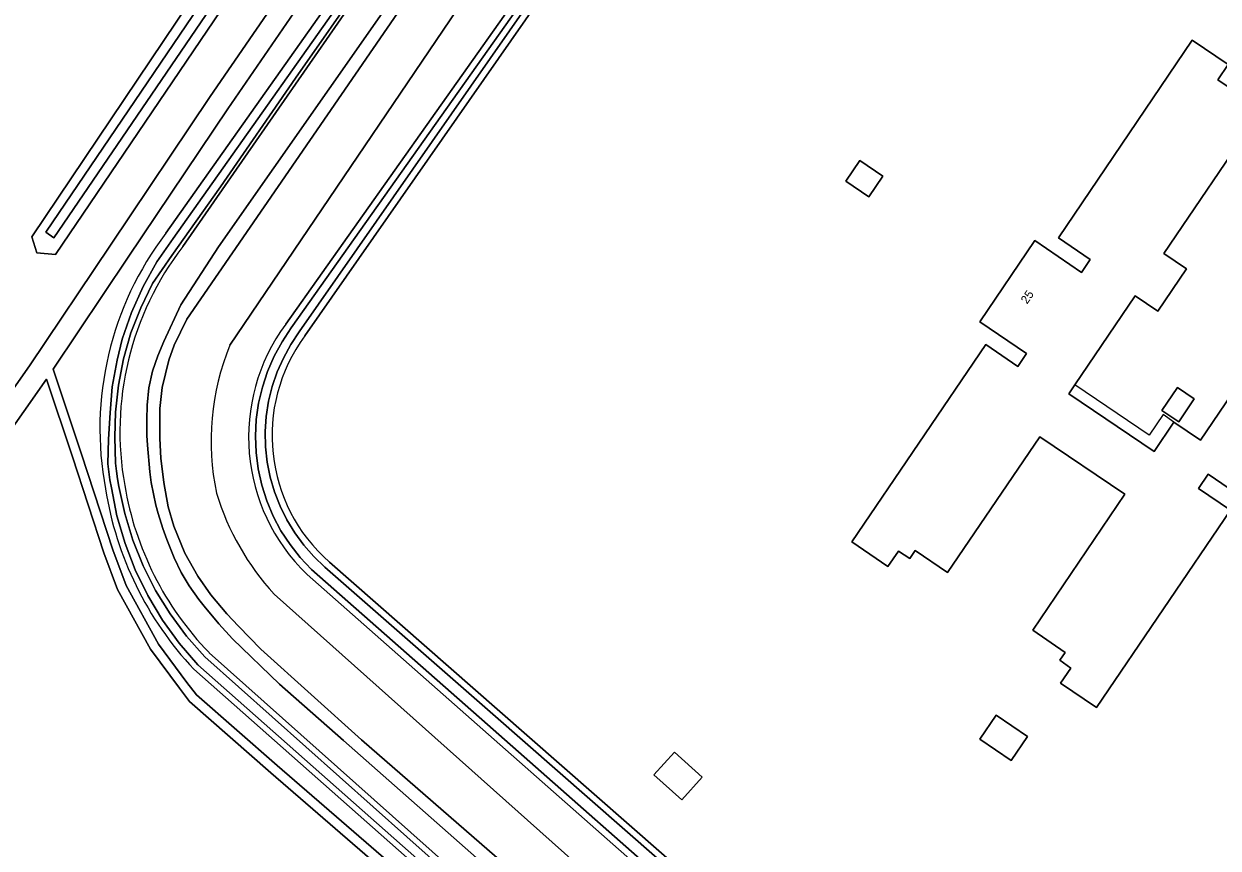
# Model space of a CAD drawing. Extents: x 158132 to 159664, y 385256 to 387218.
# Drawn here: x 159064.7 to 159204, y 386047.9 to 386144.1 of the extents above; entities that cross this region are included whole.
import ezdxf

# ---------------------------------------------------------------- set-up
doc = ezdxf.new("R2010")
doc.units = 0
for name, color, linetype in [('IMGEO_Berm_groen', 7, 'Continuous'), ('IMGEO_Erf', 7, 'Continuous'), ('IMGEO_Gemengd_bos', 7, 'Continuous'), ('IMGEO_Grasland_overig', 7, 'Continuous'), ('IMGEO_Groenvoorziening', 7, 'Continuous'), ('IMGEO_Oever', 7, 'Continuous'), ('IMGEO_Pand', 7, 'Continuous'), ('IMGEO_Pand_nummerreeks', 7, 'Continuous'), ('IMGEO_Pand_overbouw', 7, 'Continuous'), ('IMGEO_Rijbaan_lokaal_gesloten', 7, 'Continuous'), ('IMGEO_Voetpad_open', 7, 'Continuous'), ('IMGEO_Waterloop', 7, 'Continuous')]:
    doc.layers.add(name, color=color, linetype=linetype)

msp = doc.modelspace()

# ---------------------------------------------------------------- linework, layer by layer
at = {"layer": 'IMGEO_Berm_groen'}
for points in [[(159144.9, 386200.28), (159087.36, 386118.05), (159082.99, 386111.26), (159081, 386107), (159080.28, 386105.32), (159079.65, 386103.52), (159079.25, 386101.61), (159079.04, 386099.56), (159078.99, 386097.86), (159079.02, 386096.04), (159079.07, 386094.91), (159079.34, 386091.79), (159079.52, 386090.54), (159080.06, 386087.91), (159080.33, 386086.93), (159080.88, 386085.19), (159081.35, 386083.88), (159082.2, 386081.75), (159083.01, 386080.05), (159083.93, 386078.5), (159085.08, 386076.9), (159085.7, 386076.12), (159087.39, 386074.05), (159088.98, 386072.29), (159094.49, 386066.99), (159101.93, 386060.45), (159119.46, 386044.98)], [(159164.35, 386008.03), (159104.06, 386060.51), (159092.32, 386071.08), (159089.68, 386073.77), (159088.34, 386075.22), (159086.49, 386077.43), (159084.94, 386079.61), (159083.44, 386082.3), (159082.15, 386085.46), (159081.51, 386087.71), (159080.97, 386090.53), (159080.65, 386093.4), (159080.52, 386095.68), (159080.54, 386099.16), (159080.8, 386101.62), (159081.56, 386104.81), (159082.2, 386106.57), (159083.68, 386109.62), (159128.76, 386175.21)]]:
    msp.add_lwpolyline(points, dxfattribs=at)
at = {"layer": 'IMGEO_Erf'}
for points in [[(159152.42, 386199.12), (159151.33, 386197.56), (159145.82, 386189.71), (159139.74, 386181.11), (159134.25, 386173.17), (159130.26, 386167.41), (159125.6, 386160.77), (159122.73, 386156.88), (159088.69, 386106.57)], [(159095.21, 386109.04), (159154.57, 386192.95)], [(159156.49, 386192.28), (159155.21, 386190.47), (159097.43, 386107.66)], [(159210.15, 386086.51), (159202.8, 386091.5), (159201.68, 386089.84), (159205.41, 386087.3), (159189.81, 386064.27), (159185.6, 386067.11), (159186.8, 386068.88), (159185.51, 386069.79), (159186.14, 386070.7), (159182.35, 386073.29), (159193.11, 386089.17), (159183.2, 386095.88), (159172.42, 386080.03), (159168.62, 386082.6), (159168, 386081.66), (159166.68, 386082.54), (159165.46, 386080.75), (159161.26, 386083.6), (159176.87, 386106.63), (159180.63, 386104.09), (159181.64, 386105.58), (159176.18, 386109.3), (159182.6, 386118.77), (159188.06, 386115.07), (159189.07, 386116.56), (159185.34, 386119.1), (159200.96, 386142.17), (159205.17, 386139.33), (159203.95, 386137.53), (159205.26, 386136.65)], [(159208.42, 386133.13), (159197.66, 386117.28), (159200.3, 386115.48), (159196.93, 386110.52), (159194.29, 386112.31), (159187.28, 386101.94), (159186.57, 386100.9), (159196.51, 386094.17), (159198.83, 386097.59), (159201.92, 386095.5), (159207.01, 386103)], [(159100.3, 386081.25), (159119.88, 386064.08), (159173.29, 386017.26), (159178.72, 386013.24)], [(159176.12, 386011.15), (159170.28, 386015.78), (159118.22, 386061.71), (159097.7, 386079.81)], [(159093.86, 386077.52), (159130.24, 386045.01), (159167.9, 386011.78), (159171.14, 386008.92)]]:
    msp.add_lwpolyline(points, dxfattribs=at)
for points in [[(159163.24, 386123.9), (159160.56, 386125.71), (159162.19, 386128.13), (159164.87, 386126.31)], [(159197.42, 386098.96), (159199.23, 386101.64), (159201.2, 386100.31), (159199.39, 386097.63)], [(159179.82, 386058.09), (159176.18, 386060.57), (159178.1, 386063.38), (159181.73, 386060.9)], [(159141.4, 386053.51), (159138.16, 386056.44), (159140.55, 386059.08), (159143.79, 386056.15)]]:
    msp.add_lwpolyline(points, close=True, dxfattribs=at)
for centre, radius, start, end in [((159113.14, 386095.84), 22.26, 143.6506, 226.0684), ((159113.24, 386096.01), 19.63, 143.6275, 228.7695), ((159116.25, 386095.37), 29.75, 157.884, 191.7906), ((159116.46, 386098.25), 30.67, 196.9848, 222.5406)]:
    msp.add_arc(centre, radius, start, end, dxfattribs=at)
at = {"layer": 'IMGEO_Gemengd_bos'}
for points in [[(158987.13, 385983.76), (158985.38, 385985.66), (159024.58, 386045.84), (159026.86, 386049.34), (159065.31, 386104.15), (159074.76, 386118.24), (159086.39, 386135.58), (159115.48, 386177.93), (159137.05, 386210.07), (159143.29, 386219.37), (159143.28, 386220.9), (159143.27, 386223.44), (159126.17, 386240.76), (159117.05, 386250), (159112.16, 386254.95), (159110, 386256.99), (159100.09, 386266.87)], [(159108.55, 386176.55), (159068.34, 386117.14), (159066.18, 386117.34), (159065.58, 386119.22), (159105.58, 386178.72)]]:
    msp.add_lwpolyline(points, dxfattribs=at)
at = {"layer": 'IMGEO_Grasland_overig'}
msp.add_lwpolyline([(159026.34, 386043.95), (159128.6, 385934.11), (159167.77, 385991.84), (159128.38, 386026.44), (159093.47, 386056.67), (159083.99, 386064.99), (159082.8, 386066.54), (159079.43, 386071.09), (159075.57, 386078.05), (159073.99, 386082.33), (159070.33, 386093.52), (159067.29, 386102.62), (159028.94, 386047.93)], close=True, dxfattribs=at)
at = {"layer": 'IMGEO_Groenvoorziening'}
for points in [[(159081.22, 386119.64), (159143.41, 386207.64)], [(159144.68, 386206.73), (159083.19, 386118.08)], [(159119.46, 386044.98), (159101.93, 386060.45), (159094.49, 386066.99), (159088.98, 386072.29), (159087.39, 386074.05), (159085.7, 386076.12), (159085.08, 386076.9), (159083.93, 386078.5), (159083.01, 386080.05), (159082.2, 386081.75), (159081.35, 386083.88), (159080.88, 386085.19), (159080.33, 386086.93), (159080.06, 386087.91), (159079.52, 386090.54), (159079.34, 386091.79), (159079.07, 386094.91), (159079.02, 386096.04), (159078.99, 386097.86), (159079.04, 386099.56), (159079.25, 386101.61), (159079.65, 386103.52), (159080.28, 386105.32), (159081, 386107), (159082.99, 386111.26), (159087.36, 386118.05), (159144.9, 386200.28)], [(159117.55, 386176.52), (159088.46, 386134.17), (159076.84, 386116.84), (159068.07, 386103.78), (159071.38, 386093.86), (159075.04, 386082.7), (159076.58, 386078.52), (159080.36, 386071.69), (159083.69, 386067.21), (159084.8, 386065.76), (159094.2, 386057.51), (159129.11, 386027.28)], [(159086.26, 386070.68), (159109.81, 386049.69), (159165.56, 386000), (159166.27, 385999.37)], [(159164.82, 385997.74), (159162.26, 386000), (159108.37, 386047.64), (159084.47, 386068.77)]]:
    msp.add_lwpolyline(points, dxfattribs=at)
for centre, radius, start, end in [((159111.17, 386096.83), 37.64, 142.7073, 190.7888), ((159111.28, 386096.49), 35.42, 142.456, 190.2425), ((159113.52, 386096), 39.82, 188.9766, 223.1527), ((159112.88, 386096.34), 36.97, 189.5623, 223.9383)]:
    msp.add_arc(centre, radius, start, end, dxfattribs=at)
at = {"layer": 'IMGEO_Oever'}
for points in [[(159143.41, 386207.64), (159081.22, 386119.64)], [(159083.19, 386118.08), (159144.68, 386206.73)], [(159170.79, 386016.39), (159118.74, 386062.3), (159098.23, 386080.39), (159096.9, 386081.79), (159095.71, 386083.3), (159094.65, 386084.92), (159093.75, 386086.62), (159093, 386088.4), (159092.41, 386090.24), (159091.99, 386092.12), (159091.74, 386094.03), (159091.67, 386095.96), (159091.76, 386097.89), (159092.03, 386099.8), (159092.48, 386101.68), (159093.08, 386103.51), (159093.85, 386105.28), (159094.78, 386106.97), (159095.85, 386108.58), (159155.18, 386192.43)], [(159154.57, 386192.95), (159095.21, 386109.04)], [(159154.6, 386190.97), (159096.79, 386108.12), (159095.8, 386106.64), (159094.93, 386105.07), (159094.21, 386103.44), (159093.64, 386101.75), (159093.21, 386100.02), (159092.94, 386098.26), (159092.82, 386096.48), (159092.86, 386094.69), (159093.05, 386092.92), (159093.4, 386091.17), (159093.9, 386089.46), (159094.54, 386087.79), (159095.33, 386086.2), (159096.26, 386084.67), (159097.31, 386083.23), (159098.49, 386081.89), (159099.78, 386080.66), (159119.36, 386063.49), (159172.8, 386016.65)], [(159097.43, 386107.66), (159155.21, 386190.47), (159156.49, 386192.28)], [(159105.58, 386178.72), (159065.58, 386119.22), (159066.18, 386117.34), (159068.34, 386117.14), (159108.55, 386176.55)], [(159162.71, 386000.52), (159108.83, 386048.15), (159084.95, 386069.26), (159082.78, 386071.79), (159080.83, 386074.49), (159079.12, 386077.34), (159077.66, 386080.34), (159076.46, 386083.44), (159075.52, 386086.64), (159074.87, 386089.91), (159074.7, 386090.84), (159074.56, 386091.78), (159074.44, 386092.72), (159074.54, 386095.61), (159074.72, 386098.68), (159074.96, 386101.7), (159075.56, 386104.83), (159076.11, 386107.27), (159077.2, 386110.39), (159078.56, 386113.41), (159080.19, 386116.29), (159082.08, 386119.01), (159107.02, 386154.3)], [(159104.4, 386149.29), (159096.35, 386137.72), (159087.61, 386125.03), (159081.94, 386117.04), (159079.67, 386113.76), (159078.29, 386110.93), (159077.15, 386108), (159076.28, 386104.98), (159075.68, 386101.9), (159075.34, 386098.77), (159075.29, 386095.82), (159075.36, 386092.79), (159075.47, 386091.88), (159075.59, 386090.98), (159075.74, 386090.08), (159076.42, 386086.92), (159077.36, 386083.83), (159078.56, 386080.83), (159080.02, 386077.95), (159081.71, 386075.2), (159083.64, 386072.61), (159085.78, 386070.19), (159109.35, 386049.18), (159165.11, 385999.49)], [(159119.88, 386064.08), (159100.3, 386081.25)], [(159097.7, 386079.81), (159118.22, 386061.71), (159170.28, 386015.78), (159176.12, 386011.15)], [(159109.81, 386049.69), (159086.26, 386070.68)], [(159084.47, 386068.77), (159108.37, 386047.64), (159162.26, 386000), (159164.82, 385997.74)], [(159178.72, 386013.24), (159173.29, 386017.26), (159119.88, 386064.08)], [(159166.27, 385999.37), (159165.56, 386000), (159109.81, 386049.69)]]:
    msp.add_lwpolyline(points, dxfattribs=at)
msp.add_lwpolyline([(159067.24, 386119.76), (159105.86, 386176.8), (159106.98, 386176.07), (159068.16, 386119.1)], close=True, dxfattribs=at)
for centre, radius, start, end in [((159111.17, 386096.83), 37.64, 142.7073, 190.7888), ((159111.28, 386096.49), 35.42, 142.456, 190.2425), ((159113.14, 386095.84), 22.26, 143.6506, 226.0684), ((159113.24, 386096.01), 19.63, 143.6275, 228.7695), ((159113.52, 386096), 39.82, 188.9766, 223.1527), ((159112.88, 386096.34), 36.97, 189.5623, 223.9383)]:
    msp.add_arc(centre, radius, start, end, dxfattribs=at)
at = {"layer": 'IMGEO_Pand'}
for points in [[(159205.26, 386136.65), (159203.95, 386137.53), (159205.17, 386139.33), (159200.96, 386142.17), (159185.34, 386119.1), (159189.07, 386116.56), (159188.06, 386115.07), (159182.6, 386118.77), (159176.18, 386109.3), (159181.64, 386105.58), (159180.63, 386104.09), (159176.87, 386106.63), (159161.26, 386083.6), (159165.46, 386080.75), (159166.68, 386082.54), (159168, 386081.66), (159168.62, 386082.6), (159172.42, 386080.03), (159183.2, 386095.88), (159193.11, 386089.17), (159182.35, 386073.29), (159186.14, 386070.7), (159185.51, 386069.79), (159186.8, 386068.88), (159185.6, 386067.11), (159189.81, 386064.27), (159205.41, 386087.3), (159201.68, 386089.84), (159202.8, 386091.5), (159210.15, 386086.51)], [(159207.01, 386103), (159201.92, 386095.5), (159198.83, 386097.59), (159196.51, 386094.17), (159186.57, 386100.9), (159187.28, 386101.94), (159194.29, 386112.31), (159196.93, 386110.52), (159200.3, 386115.48), (159197.66, 386117.28), (159208.42, 386133.13)]]:
    msp.add_lwpolyline(points, dxfattribs=at)
for points in [[(159163.24, 386123.9), (159164.87, 386126.31), (159162.19, 386128.13), (159160.56, 386125.71)], [(159197.42, 386098.96), (159199.39, 386097.63), (159201.2, 386100.31), (159199.23, 386101.64)], [(159179.82, 386058.09), (159181.73, 386060.9), (159178.1, 386063.38), (159176.18, 386060.57)], [(159141.4, 386053.51), (159143.79, 386056.15), (159140.55, 386059.08), (159138.16, 386056.44)]]:
    msp.add_lwpolyline(points, close=True, dxfattribs=at)
at = {"layer": 'IMGEO_Pand_overbouw'}
msp.add_lwpolyline([(159187.28, 386101.94), (159186.57, 386100.9), (159196.51, 386094.17), (159198.83, 386097.59), (159197.55, 386098.46), (159195.94, 386096.08)], close=True, dxfattribs=at)
at = {"layer": 'IMGEO_Rijbaan_lokaal_gesloten'}
for points in [[(159088.69, 386106.57), (159122.73, 386156.88), (159125.6, 386160.77), (159130.26, 386167.41), (159134.25, 386173.17), (159139.74, 386181.11), (159145.82, 386189.71)], [(159128.76, 386175.21), (159083.68, 386109.62), (159082.2, 386106.57), (159081.56, 386104.81), (159080.8, 386101.62), (159080.54, 386099.16), (159080.52, 386095.68), (159080.65, 386093.4), (159080.97, 386090.53), (159081.51, 386087.71), (159082.15, 386085.46), (159083.44, 386082.3), (159084.94, 386079.61), (159086.49, 386077.43), (159088.34, 386075.22), (159089.68, 386073.77), (159092.32, 386071.08), (159104.06, 386060.51), (159164.35, 386008.03), (159167.9, 386011.78), (159130.24, 386045.01), (159093.86, 386077.52)]]:
    msp.add_lwpolyline(points, dxfattribs=at)
for centre, radius, start, end in [((159116.25, 386095.37), 29.75, 157.884, 191.7906), ((159116.46, 386098.25), 30.67, 196.9848, 222.5406)]:
    msp.add_arc(centre, radius, start, end, dxfattribs=at)
at = {"layer": 'IMGEO_Voetpad_open'}
for points in [[(159167.29, 385993.89), (159158.79, 386001.21), (159129.11, 386027.28), (159094.2, 386057.51), (159084.8, 386065.76), (159083.69, 386067.21), (159080.36, 386071.69), (159076.58, 386078.52), (159075.04, 386082.7), (159071.38, 386093.86), (159068.07, 386103.78), (159076.84, 386116.84), (159088.46, 386134.17), (159117.55, 386176.52), (159139.13, 386208.67), (159145.27, 386217.83), (159146.45, 386217.87), (159148.71, 386217.94), (159143.27, 386223.44)], [(159143.28, 386220.9), (159143.29, 386219.37), (159137.05, 386210.07), (159115.48, 386177.93), (159086.39, 386135.58), (159074.76, 386118.24), (159065.31, 386104.15), (159026.86, 386049.34)], [(159028.94, 386047.93), (159067.29, 386102.62), (159070.33, 386093.52), (159073.99, 386082.33), (159075.57, 386078.05), (159079.43, 386071.09), (159082.8, 386066.54), (159083.99, 386064.99), (159093.47, 386056.67), (159128.38, 386026.44), (159167.77, 385991.84)]]:
    msp.add_lwpolyline(points, dxfattribs=at)
at = {"layer": 'IMGEO_Waterloop'}
for points in [[(159155.18, 386192.43), (159095.85, 386108.58), (159094.78, 386106.97), (159093.85, 386105.28), (159093.08, 386103.51), (159092.48, 386101.68), (159092.03, 386099.8), (159091.76, 386097.89), (159091.67, 386095.96), (159091.74, 386094.03), (159091.99, 386092.12), (159092.41, 386090.24), (159093, 386088.4), (159093.75, 386086.62), (159094.65, 386084.92), (159095.71, 386083.3), (159096.9, 386081.79), (159098.23, 386080.39), (159118.74, 386062.3), (159170.79, 386016.39)], [(159172.8, 386016.65), (159119.36, 386063.49), (159099.78, 386080.66), (159098.49, 386081.89), (159097.31, 386083.23), (159096.26, 386084.67), (159095.33, 386086.2), (159094.54, 386087.79), (159093.9, 386089.46), (159093.4, 386091.17), (159093.05, 386092.92), (159092.86, 386094.69), (159092.82, 386096.48), (159092.94, 386098.26), (159093.21, 386100.02), (159093.64, 386101.75), (159094.21, 386103.44), (159094.93, 386105.07), (159095.8, 386106.64), (159096.79, 386108.12), (159154.6, 386190.97)], [(159107.02, 386154.3), (159082.08, 386119.01), (159080.19, 386116.29), (159078.56, 386113.41), (159077.2, 386110.39), (159076.11, 386107.27), (159075.56, 386104.83), (159074.96, 386101.7), (159074.72, 386098.68), (159074.54, 386095.61), (159074.44, 386092.72), (159074.56, 386091.78), (159074.7, 386090.84), (159074.87, 386089.91), (159075.52, 386086.64), (159076.46, 386083.44), (159077.66, 386080.34), (159079.12, 386077.34), (159080.83, 386074.49), (159082.78, 386071.79), (159084.95, 386069.26), (159108.83, 386048.15), (159162.71, 386000.52)], [(159165.11, 385999.49), (159109.35, 386049.18), (159085.78, 386070.19), (159083.64, 386072.61), (159081.71, 386075.2), (159080.02, 386077.95), (159078.56, 386080.83), (159077.36, 386083.83), (159076.42, 386086.92), (159075.74, 386090.08), (159075.59, 386090.98), (159075.47, 386091.88), (159075.36, 386092.79), (159075.29, 386095.82), (159075.34, 386098.77), (159075.68, 386101.9), (159076.28, 386104.98), (159077.15, 386108), (159078.29, 386110.93), (159079.67, 386113.76), (159081.94, 386117.04), (159087.61, 386125.03), (159096.35, 386137.72), (159104.4, 386149.29)]]:
    msp.add_lwpolyline(points, dxfattribs=at)
msp.add_lwpolyline([(159067.24, 386119.76), (159068.16, 386119.1), (159106.98, 386176.07), (159105.86, 386176.8)], close=True, dxfattribs=at)

# ---------------------------------------------------------------- texts
at = {"layer": 'IMGEO_Pand_nummerreeks'}
msp.add_text('25', height=1, rotation=55.8347, dxfattribs=at).set_placement((159181.7, 386111.3))

doc.saveas('drawing.dxf')
